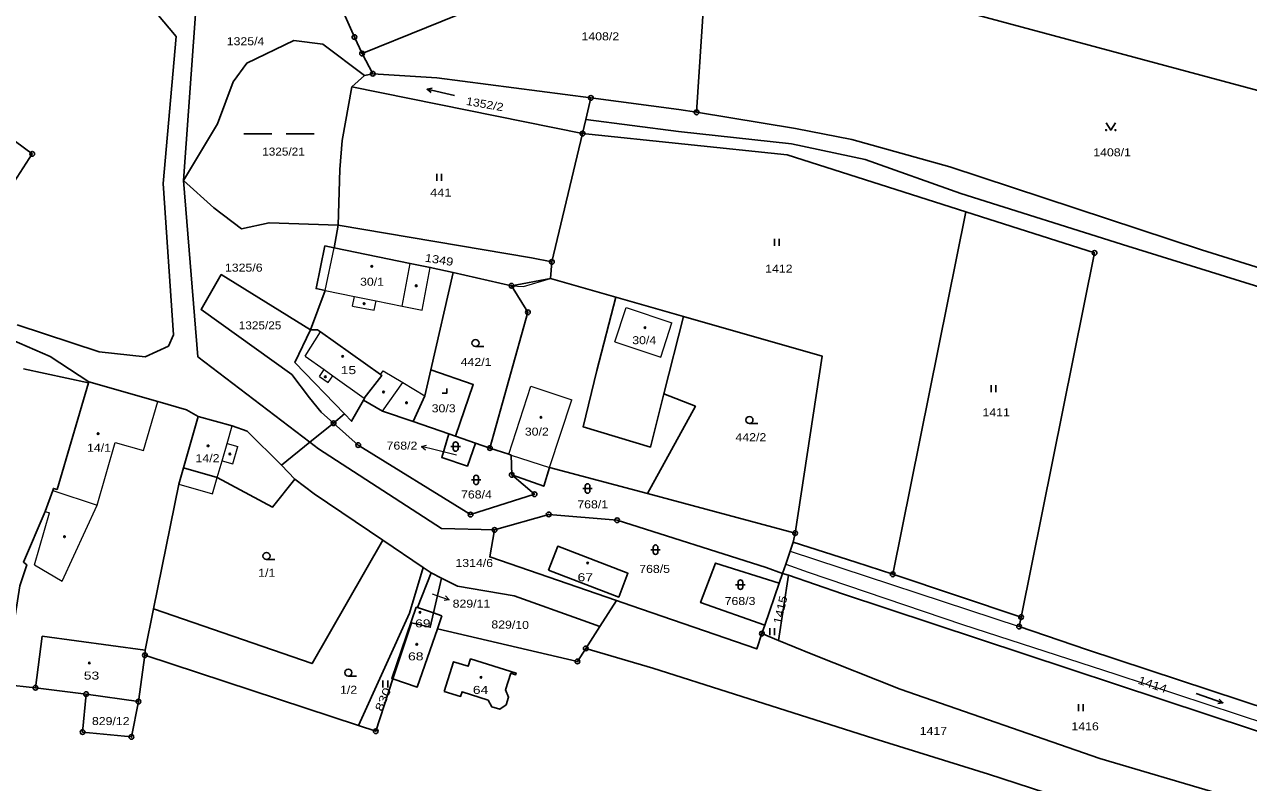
# Model space of a CAD drawing. Extents: x -872229 to -869198, y -1075981 to -1074329.
# Drawn here: x -870924.3 to -870664.3, y -1075366 to -1075205 of the extents above; entities that cross this region are included whole.
import ezdxf
from ezdxf.enums import TextEntityAlignment as Align

# ---------------------------------------------------------------- set-up
doc = ezdxf.new("R2010")
doc.units = 0
doc.header["$LTSCALE"] = 0.68
for name, color, linetype, lineweight in [('1', 7, 'Continuous', 25), ('3', 7, 'Continuous', 25), ('4', 7, 'Continuous', 13), ('5', 7, 'Continuous', 25), ('7', 7, 'Continuous', 13), ('8', 7, 'Continuous', 25)]:
    doc.layers.add(name, color=color, linetype=linetype, lineweight=lineweight)
doc.layers.add('2', color=7, linetype='Continuous')

msp = doc.modelspace()

# ---------------------------------------------------------------- linework, layer by layer
at = {"layer": '1'}
for p, q in [((-870784.32, -1075186.07), (-870610.3, -1075233.15)), ((-870850.35, -1075215.5), (-870852.61, -1075211.21)), ((-870854.77, -1075218.26), (-870852.13, -1075215.85)), ((-870857.69, -1075247.67), (-870858.56, -1075252.46)), ((-870838.03, -1075278.35), (-870833.27, -1075257.72)), ((-870788.49, -1075283.45), (-870784.32, -1075267.06)), ((-870910.7, -1075281.16), (-870924.55, -1075278.18)), ((-870858.68, -1075289.72), (-870856.35, -1075287.73)), ((-870858.68, -1075289.72), (-870863.7, -1075293.77)), ((-870869.76, -1075298.66), (-870863.7, -1075293.77)), ((-870866.86, -1075301.57), (-870869.76, -1075298.66)), ((-870791.98, -1075304.67), (-870760.65, -1075313.06)), ((-870837.92, -1075321.5), (-870839.61, -1075320.36)), ((-870835.78, -1075322.6), (-870837.92, -1075321.5)), ((-870837.44, -1075330.01), (-870835.78, -1075322.6)), ((-870898.66, -1075337.89), (-870896.88, -1075329.11)), ((-870840.85, -1075328.89), (-870837.44, -1075330.01)), ((-870842.12, -1075332.11), (-870846.05, -1075344.03)), ((-870837.44, -1075330.01), (-870835.64, -1075330.6)), ((-870835.64, -1075330.6), (-870836.61, -1075333.39)), ((-870898.66, -1075337.89), (-870898.74, -1075339.01)), ((-870898.74, -1075339.01), (-870853.39, -1075353.92)), ((-870921.99, -1075345.91), (-870928.54, -1075345.19))]:
    msp.add_line(p, q, dxfattribs=at)
for points in [[(-870852.61, -1075211.21), (-870811.58, -1075194.57), (-870784.32, -1075186.07)], [(-870811.58, -1075194.57), (-870779.53, -1075192.5), (-870781.56, -1075223.68)], [(-870882.08, -1075195.84), (-870887.87, -1075200.84), (-870890.54, -1075238.17)], [(-870925.85, -1075268.83), (-870908.47, -1075274.58), (-870898.66, -1075275.61), (-870893.76, -1075273.35), (-870892.7, -1075270.97), (-870894.88, -1075238.8), (-870892.1, -1075207.59), (-870896.18, -1075202.7), (-870909.34, -1075202.24), (-870920.27, -1075200.54), (-870931.8, -1075197.32)], [(-870852.61, -1075211.21), (-870854.23, -1075207.71), (-870856.49, -1075202.6)], [(-870890.54, -1075238.17), (-870883.32, -1075226.14), (-870879.96, -1075217.21), (-870877.12, -1075213.23), (-870867.09, -1075208.41), (-870860.94, -1075209.18), (-870852.13, -1075215.85), (-870850.35, -1075215.5)], [(-870804.02, -1075220.62), (-870836.74, -1075216.34), (-870850.35, -1075215.5)], [(-870857.69, -1075247.67), (-870816.62, -1075254.62), (-870812.3, -1075255.46), (-870805.78, -1075228.2), (-870854.77, -1075218.26)], [(-870854.77, -1075218.26), (-870856.87, -1075229.66), (-870857.34, -1075235.8), (-870857.69, -1075247.67)], [(-870805.78, -1075228.2), (-870805.08, -1075225.21), (-870804.02, -1075220.62)], [(-870781.56, -1075223.68), (-870785.37, -1075223.06), (-870804.02, -1075220.62)], [(-870805.08, -1075225.21), (-870785.38, -1075227.74), (-870761.4, -1075230.4), (-870745.77, -1075233.67), (-870725.43, -1075240.95), (-870689.94, -1075252.08), (-870636.2, -1075268.85), (-870577.25, -1075287.24), (-870525.79, -1075303.65), (-870498.58, -1075312.54)], [(-870484.94, -1075312.75), (-870507.19, -1075305.67), (-870536.45, -1075296.46), (-870573.82, -1075284.57), (-870611.19, -1075272.67), (-870674.35, -1075252.89), (-870727.76, -1075235.26), (-870748.62, -1075229.44), (-870760.57, -1075227.08), (-870781.56, -1075223.68)], [(-870805.78, -1075228.2), (-870762.33, -1075232.72), (-870724.39, -1075244.81)], [(-871072.01, -1075232.97), (-871066.83, -1075229.86), (-871050.73, -1075230.05), (-871024.91, -1075235.65), (-871004.91, -1075242.17), (-870984.75, -1075250.58), (-870962.8, -1075257.63), (-870944.86, -1075263.23), (-870926.98, -1075271.99), (-870918.87, -1075275.55), (-870910.63, -1075280.9)], [(-870863.7, -1075293.77), (-870887.53, -1075275.59), (-870890.54, -1075238.17)], [(-870890.54, -1075238.17), (-870884.1, -1075243.98), (-870878.24, -1075248.43), (-870872.37, -1075247.14), (-870857.69, -1075247.67)], [(-870724.39, -1075244.81), (-870739.92, -1075321.81), (-870712.65, -1075330.89)], [(-870724.39, -1075244.81), (-870697.05, -1075253.53), (-870712.65, -1075330.89)], [(-870858.56, -1075252.46), (-870860.52, -1075252.06), (-870862.38, -1075261.13), (-870860.42, -1075261.53), (-870863.57, -1075269.88)], [(-870833.27, -1075257.72), (-870838.15, -1075256.62), (-870842.37, -1075255.78), (-870858.56, -1075252.46)], [(-870833.27, -1075257.72), (-870820.86, -1075260.51), (-870812.59, -1075258.97), (-870812.3, -1075255.46)], [(-870858.68, -1075289.72), (-870861.31, -1075287.4), (-870863.81, -1075284.33), (-870867.54, -1075279.36), (-870886.81, -1075265.58), (-870882.51, -1075258.13), (-870863.57, -1075269.88)], [(-870812.59, -1075258.97), (-870798.73, -1075262.94), (-870784.32, -1075267.06)], [(-870820.86, -1075260.51), (-870817.4, -1075266.16), (-870825.46, -1075294.99)], [(-870788.49, -1075283.45), (-870791.37, -1075294.77), (-870805.69, -1075290.46), (-870802.78, -1075278.5), (-870798.73, -1075262.94)], [(-870784.32, -1075267.06), (-870754.88, -1075275.48), (-870760.65, -1075313.06), (-870761.04, -1075314.99)], [(-870863.57, -1075269.88), (-870866.86, -1075276.84), (-870856.35, -1075287.73)], [(-870863.57, -1075269.88), (-870862.1, -1075269.86), (-870861.44, -1075270.33), (-870848.69, -1075279.37), (-870848.43, -1075279.55), (-870852.2, -1075284.38), (-870852.07, -1075284.47), (-870852.32, -1075284.82)], [(-870841.73, -1075289.35), (-870839.31, -1075283.9), (-870838.03, -1075278.35)], [(-870832.79, -1075292.45), (-870828.99, -1075281.49), (-870838.03, -1075278.35)], [(-870910.7, -1075281.16), (-870917.39, -1075303.79), (-870918.16, -1075303.57), (-870918.31, -1075303.99), (-870919.9, -1075308.44)], [(-870887.42, -1075288.26), (-870889.87, -1075286.84), (-870896.02, -1075285.08), (-870910.63, -1075280.9), (-870910.7, -1075281.16)], [(-870856.35, -1075287.73), (-870854.84, -1075289.29), (-870852.32, -1075284.82)], [(-870852.32, -1075284.82), (-870848.28, -1075287.16), (-870841.73, -1075289.35)], [(-870791.98, -1075304.67), (-870781.81, -1075286.11), (-870788.49, -1075283.45)], [(-870869.76, -1075298.66), (-870877.02, -1075291.38), (-870880.21, -1075290.3), (-870887.42, -1075288.26), (-870890.53, -1075299.22)], [(-870820.81, -1075300.7), (-870815.99, -1075304.8), (-870829.56, -1075309.11), (-870853.43, -1075294.36), (-870858.68, -1075289.72)], [(-870841.73, -1075289.35), (-870834.19, -1075291.97), (-870832.79, -1075292.45)], [(-870834.19, -1075291.97), (-870835.68, -1075297.01), (-870830.23, -1075298.81), (-870828.5, -1075293.94)], [(-870832.79, -1075292.45), (-870828.5, -1075293.94), (-870825.46, -1075294.99)], [(-870863.7, -1075293.77), (-870861.84, -1075295.19), (-870835.74, -1075312.07), (-870824.47, -1075312.39)], [(-870825.46, -1075294.99), (-870821.46, -1075296.31), (-870820.92, -1075296.51), (-870820.81, -1075300.7)], [(-870896.88, -1075329.11), (-870891.52, -1075302.69), (-870890.53, -1075299.22)], [(-870890.53, -1075299.22), (-870883.4, -1075301.25), (-870871.64, -1075307.56), (-870866.86, -1075301.57)], [(-870820.81, -1075300.7), (-870814.03, -1075303.11), (-870812.79, -1075299.09), (-870791.98, -1075304.67)], [(-870866.86, -1075301.57), (-870862.82, -1075304.74), (-870848.21, -1075314.58), (-870839.61, -1075320.36)], [(-870919.9, -1075308.44), (-870924.53, -1075319.22), (-870923.81, -1075319.83), (-870925.29, -1075324.27), (-870928.54, -1075345.19)], [(-870824.47, -1075312.39), (-870812.98, -1075309.08), (-870798.44, -1075310.32), (-870766.82, -1075320.38), (-870763.32, -1075321.65)], [(-870798.57, -1075327.39), (-870825.5, -1075318.12), (-870824.47, -1075312.39)], [(-870712.65, -1075330.89), (-870713.06, -1075332.91), (-870698.73, -1075337.79), (-870659.43, -1075350.77), (-870647.08, -1075354.82), (-870636.39, -1075356.51), (-870628.42, -1075355.25), (-870617.68, -1075352.56), (-870583.59, -1075341.47), (-870525.05, -1075322.56), (-870498.58, -1075312.54)], [(-870848.21, -1075314.58), (-870863.23, -1075340.76), (-870896.88, -1075329.11)], [(-870761.04, -1075314.99), (-870761.68, -1075316.88), (-870762.63, -1075319.63), (-870763.32, -1075321.65), (-870762.07, -1075321.97)], [(-870761.04, -1075314.99), (-870747.73, -1075319.21), (-870739.92, -1075321.81)], [(-870839.61, -1075320.36), (-870842.55, -1075330.06), (-870853.39, -1075353.92)], [(-870846.05, -1075344.03), (-870846.3, -1075343.95), (-870841.1, -1075328.81), (-870840.85, -1075328.89), (-870837.92, -1075321.5)], [(-870764.02, -1075323.7), (-870777.56, -1075319.43), (-870780.71, -1075327.83), (-870767.06, -1075332.59)], [(-870763.32, -1075321.65), (-870764.02, -1075323.7), (-870767.06, -1075332.59), (-870767.68, -1075334.4), (-870764.18, -1075335.84), (-870762.07, -1075321.97)], [(-870835.78, -1075322.6), (-870832.36, -1075324.35), (-870820.31, -1075326.41), (-870805.66, -1075331.61), (-870802.09, -1075332.87)], [(-870762.07, -1075321.97), (-870750.55, -1075325.97), (-870644.01, -1075361.21), (-870635.72, -1075362.14)], [(-870798.57, -1075327.39), (-870802.09, -1075332.87), (-870805.1, -1075337.55)], [(-870798.57, -1075327.39), (-870795.56, -1075328.43), (-870768.8, -1075337.66), (-870767.68, -1075334.4)], [(-870837.44, -1075330.01), (-870838.12, -1075333.04), (-870842.12, -1075332.11)], [(-870846.05, -1075344.03), (-870840.88, -1075345.75), (-870836.61, -1075333.39)], [(-870836.61, -1075333.39), (-870806.88, -1075340.32), (-870805.1, -1075337.55)], [(-870898.66, -1075337.89), (-870920.55, -1075334.96), (-870921.99, -1075345.91)], [(-870764.18, -1075335.84), (-870757.26, -1075338.7), (-870738.34, -1075346.2), (-870695.93, -1075360.93), (-870670.53, -1075368.46), (-870660.23, -1075373.2), (-870649.84, -1075380.47), (-870640.68, -1075391.97)], [(-870921.99, -1075345.91), (-870911.24, -1075347.26), (-870900.1, -1075348.84), (-870898.74, -1075339.01)], [(-870805.1, -1075337.55), (-870790.85, -1075341.74), (-870773.54, -1075347.26), (-870743.94, -1075356.68), (-870719.6, -1075364.23), (-870689.31, -1075374.07), (-870671.81, -1075380.32), (-870663.52, -1075383.76), (-870658.58, -1075387.02), (-870652.84, -1075392.9), (-870644.86, -1075404.62), (-870633.82, -1075423.29), (-870622.61, -1075439.76), (-870615.24, -1075449.79), (-870605.9, -1075460.53), (-870599.41, -1075465.72), (-870590.82, -1075469.8), (-870575.95, -1075474.7)], [(-870853.39, -1075353.92), (-870849.71, -1075355.13), (-870846.05, -1075344.03)], [(-870911.24, -1075347.26), (-870911.97, -1075355.32), (-870901.6, -1075356.36), (-870900.1, -1075348.84)]]:
    msp.add_lwpolyline(points, dxfattribs=at)
for points in [[(-870939.42, -1075220.15), (-870948.22, -1075229.84), (-870930.39, -1075244.42), (-870922.66, -1075232.5)], [(-870812.99, -1075320.94), (-870811.04, -1075315.85), (-870796.14, -1075321.57), (-870798.09, -1075326.66)], [(-870835.15, -1075346.69), (-870833.2, -1075340.38), (-870830.05, -1075341.35), (-870829.57, -1075339.79), (-870819.89, -1075342.79), (-870820.01, -1075343.15), (-870821.02, -1075342.83), (-870822.13, -1075346.38), (-870821.48, -1075347.92), (-870822.01, -1075349.53), (-870823.39, -1075350.47), (-870825.02, -1075349.98), (-870825.84, -1075348.52), (-870831.38, -1075346.75), (-870831.7, -1075347.75)]]:
    msp.add_lwpolyline(points, close=True, dxfattribs=at)
at = {"layer": '3'}
for p, q in [((-870838.798, -1075218.783), (-870837.733, -1075218.514)), ((-870877.759, -1075228.27), (-870871.759, -1075228.27)), ((-870868.759, -1075228.27), (-870862.759, -1075228.27)), ((-870836.751, -1075238.26), (-870836.751, -1075236.76)), ((-870835.75, -1075238.26), (-870835.75, -1075236.76)), ((-870765.051, -1075252.05), (-870765.051, -1075250.55)), ((-870764.05, -1075252.05), (-870764.05, -1075250.55)), ((-870828.523, -1075273.44), (-870826.773, -1075273.44)), ((-870719.011, -1075283.15), (-870719.011, -1075281.65)), ((-870718.01, -1075283.15), (-870718.01, -1075281.65)), ((-870770.343, -1075289.79), (-870768.593, -1075289.79)), ((-870833.741, -1075294.671), (-870831.739, -1075294.671)), ((-870833.241, -1075294.171), (-870833.241, -1075295.172)), ((-870832.239, -1075295.172), (-870832.239, -1075294.171)), ((-870829.391, -1075301.751), (-870827.389, -1075301.751)), ((-870828.891, -1075301.251), (-870828.891, -1075302.252)), ((-870827.889, -1075302.252), (-870827.889, -1075301.251)), ((-870805.721, -1075303.581), (-870803.719, -1075303.581)), ((-870805.221, -1075303.081), (-870805.221, -1075304.082)), ((-870804.219, -1075304.082), (-870804.219, -1075303.081)), ((-870791.281, -1075316.581), (-870789.279, -1075316.581)), ((-870790.781, -1075316.081), (-870790.781, -1075317.082)), ((-870789.779, -1075317.082), (-870789.779, -1075316.081)), ((-870872.913, -1075318.67), (-870871.163, -1075318.67)), ((-870773.271, -1075324.011), (-870771.269, -1075324.011)), ((-870772.771, -1075323.511), (-870772.771, -1075324.512)), ((-870771.769, -1075324.512), (-870771.769, -1075323.511)), ((-870766.021, -1075334.75), (-870766.021, -1075333.25)), ((-870765.02, -1075334.75), (-870765.02, -1075333.25)), ((-870855.533, -1075343.45), (-870853.783, -1075343.45)), ((-870848.171, -1075345.86), (-870848.171, -1075344.36)), ((-870847.17, -1075345.86), (-870847.17, -1075344.36)), ((-870700.451, -1075350.89), (-870700.451, -1075349.39)), ((-870699.45, -1075350.89), (-870699.45, -1075349.39)), ((-870669.79, -1075349.09), (-870670.877, -1075349.246))]:
    msp.add_line(p, q, dxfattribs=at)
for points in [[(-870832.952, -1075220.133), (-870838.798, -1075218.783), (-870837.959, -1075219.491)], [(-870694.6, -1075225.939), (-870693.6, -1075227.44), (-870692.6, -1075225.939)], [(-870835.591, -1075283.33), (-870834.59, -1075283.33), (-870834.59, -1075282.33)], [(-870675.463, -1075347.137), (-870669.79, -1075349.09), (-870670.551, -1075348.298)]]:
    msp.add_lwpolyline(points, dxfattribs=at)
for centre, radius in [((-870694.6, -1075227.4395), 0.1), ((-870692.6, -1075227.4395), 0.1), ((-870828.5229, -1075272.6898), 0.75), ((-870770.3429, -1075289.0398), 0.75), ((-870872.9129, -1075317.9198), 0.75), ((-870855.5329, -1075342.6998), 0.75)]:
    msp.add_circle(centre, radius, dxfattribs=at)
for centre, start, end in [((-870832.74, -1075294.1709), 0, 180), ((-870832.74, -1075295.1709), 180, 359.98789), ((-870828.39, -1075301.2509), 0, 180), ((-870828.39, -1075302.2509), 180, 359.98789), ((-870804.72, -1075303.0809), 0, 180), ((-870804.72, -1075304.0809), 180, 359.98789), ((-870790.28, -1075316.0809), 0, 180), ((-870790.28, -1075317.0809), 180, 359.98789), ((-870772.27, -1075323.5109), 0, 180), ((-870772.27, -1075324.5109), 180, 359.98789)]:
    msp.add_arc(centre, 0.5, start, end, dxfattribs=at)
at = {"layer": '4'}
for p, q in [((-870860.42, -1075261.53), (-870858.56, -1075252.46)), ((-870844.1, -1075264.84), (-870842.37, -1075255.78)), ((-870839.87, -1075265.69), (-870838.15, -1075256.62)), ((-870860.42, -1075261.53), (-870854.21, -1075262.79)), ((-870854.65, -1075264.85), (-870850.05, -1075265.73)), ((-870844.1, -1075264.84), (-870839.87, -1075265.69)), ((-870798.93, -1075272.46), (-870796.52, -1075265.16)), ((-870796.52, -1075265.16), (-870786.8, -1075268.38)), ((-870789.18, -1075275.68), (-870786.8, -1075268.38)), ((-870864.7, -1075275.44), (-870861.44, -1075270.33)), ((-870798.93, -1075272.46), (-870789.18, -1075275.68)), ((-870864.7, -1075275.44), (-870860.66, -1075278.33)), ((-870861.69, -1075279.77), (-870859.85, -1075281.09)), ((-870848.69, -1075279.37), (-870848.13, -1075278.57)), ((-870848.13, -1075278.57), (-870843.98, -1075281.08)), ((-870848.28, -1075287.16), (-870843.98, -1075281.08)), ((-870843.98, -1075281.08), (-870839.31, -1075283.9)), ((-870821.46, -1075296.31), (-870816.74, -1075281.81)), ((-870816.74, -1075281.81), (-870808.05, -1075284.73)), ((-870899.02, -1075295.53), (-870896.02, -1075285.08)), ((-870812.79, -1075299.09), (-870808.05, -1075284.73)), ((-870881.29, -1075294.02), (-870880.21, -1075290.3)), ((-870880.04, -1075298.35), (-870878.97, -1075294.69)), ((-870820.92, -1075296.51), (-870812.79, -1075299.09)), ((-870918.31, -1075303.99), (-870908.88, -1075307.14)), ((-870922.2, -1075319.79), (-870918.98, -1075308.77)), ((-870919.9, -1075308.44), (-870918.98, -1075308.77)), ((-870916.32, -1075323.29), (-870908.88, -1075307.14)), ((-870761.68, -1075316.88), (-870713.06, -1075332.91)), ((-870922.2, -1075319.79), (-870916.32, -1075323.29)), ((-870725.1, -1075332.47), (-870692.51, -1075343.01)), ((-870692.51, -1075343.01), (-870660.32, -1075353.61))]:
    msp.add_line(p, q, dxfattribs=at)
for points in [[(-870820.86, -1075260.51), (-870818.3, -1075260.71), (-870812.59, -1075258.97)], [(-870854.65, -1075264.85), (-870854.21, -1075262.79), (-870849.64, -1075263.72)], [(-870850.05, -1075265.73), (-870849.64, -1075263.72), (-870844.1, -1075264.84)], [(-870861.69, -1075279.77), (-870860.66, -1075278.33), (-870858.82, -1075279.65)], [(-870859.85, -1075281.09), (-870858.82, -1075279.65), (-870852.2, -1075284.38)], [(-870908.88, -1075307.14), (-870905.02, -1075293.81), (-870899.02, -1075295.53)], [(-870882.36, -1075297.68), (-870881.29, -1075294.02), (-870878.97, -1075294.69)], [(-870891.52, -1075302.69), (-870884.41, -1075304.73), (-870883.4, -1075301.25), (-870882.36, -1075297.68), (-870880.04, -1075298.35)], [(-870762.63, -1075319.63), (-870757.87, -1075321.38), (-870725.1, -1075332.47)]]:
    msp.add_lwpolyline(points, dxfattribs=at)
at = {"layer": '5'}
for centre in [(-870850.5468, -1075256.4092), (-870841.1168, -1075260.5292), (-870852.1768, -1075264.3292), (-870792.5368, -1075269.4292), (-870856.7368, -1075275.5092), (-870860.4268, -1075279.8492), (-870848.0568, -1075283.0992), (-870843.1768, -1075285.3792), (-870814.6068, -1075288.4492), (-870908.6768, -1075291.9292), (-870885.3168, -1075294.5192), (-870880.6968, -1075296.2492), (-870915.8168, -1075313.8192), (-870804.7168, -1075319.4192), (-870840.3268, -1075329.8992), (-870840.9968, -1075336.6792), (-870910.5268, -1075340.6392), (-870827.3568, -1075343.6992)]:
    msp.add_circle(centre, 0.175, dxfattribs=at)
at = {"layer": '7'}
for p, q in [((-870839.992, -1075294.644), (-870839.141, -1075295.372)), ((-870834.083, -1075327.197), (-870834.866, -1075326.398))]:
    msp.add_line(p, q, dxfattribs=at)
for points in [[(-870832.55, -1075296.49), (-870837.08, -1075295.37), (-870839.992, -1075294.644), (-870838.899, -1075294.4)], [(-870837.73, -1075325.94), (-870836.92, -1075326.22), (-870834.083, -1075327.197), (-870835.192, -1075327.344)]]:
    msp.add_lwpolyline(points, dxfattribs=at)
at = {"layer": '8'}
for centre, radius in [((-870854.23, -1075207.7099), 0.5), ((-870854.23, -1075207.7099), 0.0303), ((-870852.61, -1075211.2099), 0.5), ((-870852.61, -1075211.2099), 0.0303), ((-870850.35, -1075215.4999), 0.5), ((-870850.35, -1075215.4999), 0.0303), ((-870804.02, -1075220.6199), 0.5), ((-870804.02, -1075220.6199), 0.0303), ((-870781.56, -1075223.6799), 0.5), ((-870781.56, -1075223.6799), 0.0303), ((-870805.78, -1075228.1999), 0.5), ((-870805.78, -1075228.1999), 0.0303), ((-870922.66, -1075232.4999), 0.5), ((-870922.66, -1075232.4999), 0.0303), ((-870697.05, -1075253.5299), 0.5), ((-870697.05, -1075253.5299), 0.0303), ((-870812.3, -1075255.4599), 0.5), ((-870812.3, -1075255.4599), 0.0303), ((-870820.86, -1075260.5099), 0.5), ((-870820.86, -1075260.5099), 0.0303), ((-870817.4, -1075266.1599), 0.5), ((-870817.4, -1075266.1599), 0.0303), ((-870858.68, -1075289.7199), 0.5), ((-870858.68, -1075289.7199), 0.0303), ((-870853.43, -1075294.3599), 0.5), ((-870853.43, -1075294.3599), 0.0303), ((-870825.46, -1075294.9899), 0.5), ((-870825.46, -1075294.9899), 0.0303), ((-870820.81, -1075300.6999), 0.5), ((-870820.81, -1075300.6999), 0.0303), ((-870815.99, -1075304.7999), 0.5), ((-870815.99, -1075304.7999), 0.0303), ((-870829.56, -1075309.1099), 0.5), ((-870812.98, -1075309.0799), 0.5), ((-870829.56, -1075309.1099), 0.0303), ((-870812.98, -1075309.0799), 0.0303), ((-870798.44, -1075310.3199), 0.5), ((-870798.44, -1075310.3199), 0.0303), ((-870824.47, -1075312.3899), 0.5), ((-870824.47, -1075312.3899), 0.0303), ((-870760.65, -1075313.0599), 0.5), ((-870760.65, -1075313.0599), 0.0303), ((-870739.92, -1075321.8099), 0.5), ((-870739.92, -1075321.8099), 0.0303), ((-870712.65, -1075330.8899), 0.5), ((-870712.65, -1075330.8899), 0.0303), ((-870767.68, -1075334.3999), 0.5), ((-870767.68, -1075334.3999), 0.0303), ((-870713.06, -1075332.9099), 0.5), ((-870713.06, -1075332.9099), 0.0303), ((-870805.1, -1075337.5499), 0.5), ((-870898.74, -1075339.0099), 0.5), ((-870898.74, -1075339.0099), 0.0303), ((-870806.88, -1075340.3199), 0.5), ((-870805.1, -1075337.5499), 0.0303), ((-870806.88, -1075340.3199), 0.0303), ((-870921.99, -1075345.9099), 0.5), ((-870921.99, -1075345.9099), 0.0303), ((-870911.24, -1075347.2599), 0.5), ((-870911.24, -1075347.2599), 0.0303), ((-870900.1, -1075348.8399), 0.5), ((-870900.1, -1075348.8399), 0.0303), ((-870911.97, -1075355.3199), 0.5), ((-870911.97, -1075355.3199), 0.0303), ((-870849.71, -1075355.1299), 0.5), ((-870849.71, -1075355.1299), 0.0303), ((-870901.6, -1075356.3599), 0.5), ((-870901.6, -1075356.3599), 0.0303)]:
    msp.add_circle(centre, radius, dxfattribs=at)

# ---------------------------------------------------------------- texts
at = {"layer": '2'}
for s, width, p in [('1408/2', 1.15, (-870802.009, -1075208.39)), ('1408/1', 1.15, (-870693.319, -1075233.03)), ('768/2', 1.15, (-870844.139, -1075295.32)), ('1/1', 1.15, (-870872.86, -1075322.34)), ('67', 1.3, (-870805.21, -1075323.28)), ('69', 1.3, (-870839.72, -1075333.08)), ('68', 1.3, (-870841.21, -1075340.09)), ('1/2', 1.15, (-870855.48, -1075347.18)), ('64', 1.3, (-870827.45, -1075347.21))]:
    msp.add_text(s, height=1.7, dxfattribs=dict(at, width=width)).set_placement(p, align=Align.CENTER)
for s, width, p in [('1325/4', 1.15, (-870881.36, -1075209.43)), ('1325/21', 1.1, (-870873.82, -1075232.87)), ('441', 1.2, (-870838.16, -1075241.58)), ('1325/6', 1.15, (-870881.74, -1075257.52)), ('1412', 1.15, (-870767, -1075257.74)), ('30/1', 1.15, (-870853.04, -1075260.51)), ('1325/25', 1.1, (-870878.8, -1075269.78)), ('30/4', 1.15, (-870795.23, -1075272.93)), ('15', 1.3, (-870857.16, -1075279.29)), ('442/1', 1.15, (-870831.67, -1075277.55)), ('30/3', 1.15, (-870837.83, -1075287.4)), ('1411', 1.15, (-870720.85, -1075288.26)), ('30/2', 1.15, (-870818.05, -1075292.35)), ('442/2', 1.15, (-870773.3, -1075293.53)), ('14/1', 1.15, (-870911.03, -1075295.79)), ('14/2', 1.15, (-870887.98, -1075297.99)), ('768/4', 1.15, (-870831.6, -1075305.7)), ('768/1', 1.15, (-870806.9, -1075307.79)), ('1314/6', 1.15, (-870832.79, -1075320.25)), ('768/5', 1.15, (-870793.75, -1075321.51)), ('829/11', 1.15, (-870833.38, -1075328.884)), ('768/3', 1.15, (-870775.61, -1075328.33)), ('53', 1.3, (-870911.72, -1075344.17)), ('829/12', 1.15, (-870909.99, -1075353.83)), ('1417', 1.15, (-870734.18, -1075355.93)), ('1416', 1.15, (-870701.96, -1075354.95))]:
    msp.add_text(s, height=1.7, dxfattribs=dict(at, width=width)).set_placement(p)
for s, rotation, width, p in [('1352/2', 350, 1.15, (-870830.617, -1075222.077)), ('1349', 351, 1.2, (-870839.372, -1075255.369)), ('1415', 77, 1.2, (-870763.621, -1075332.521)), ('829/10', 359, 1.15, (-870825.174, -1075333.289)), ('1414', 341, 1.25, (-870687.966, -1075344.993)), ('830', 67, 1.35, (-870848.377, -1075351.052))]:
    msp.add_text(s, height=1.7, rotation=rotation, dxfattribs=dict(at, width=width)).set_placement(p)

doc.saveas('drawing.dxf')
